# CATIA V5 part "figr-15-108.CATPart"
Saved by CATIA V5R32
Part number: Part1
Bounding box of the stored display mesh (mm): x -60.955 to 60.955, y -33.748 to 33.748, z 0 to 6.052
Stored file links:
  D:\PROJECTS\Project 2022\CATIA V5 6R 2022\Resources\Part Files\c15_catia_v5_6r2022_prt\figr-15-108.CATPart
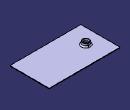
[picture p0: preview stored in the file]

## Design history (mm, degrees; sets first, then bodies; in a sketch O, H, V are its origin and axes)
SheetMetalParameters1: Thickness 1, BendRadius 5, KFactor 0.5 {= log(min(100,max(20*SheetMetalParameters1.BendRadius,SheetMetalParameters1.Thickness)/SheetMetalParameters1.Thickness))/log(100)/2}, ReliefRadialLength 1, ReliefAxialLength 2, MinimumBendRadius 0
Body1 (main body)
  Sketch1 on xy-plane, origin (0, 0, 0), H (1, 0, 0), V (0, 1, 0)
    line L1 (60.9549, 33.7477) -> (60.9549, -33.7477)
    line L2 (60.9549, -33.7477) -> (-60.9549, -33.7477)
    line L3 (-60.9549, -33.7477) -> (-60.9549, 33.7477)
    line L4 (-60.9549, 33.7477) -> (60.9549, 33.7477)
    vertical: L1 V, L3 V
    horizontal: L2 H, L4 H
    equidistance: L1 L3 O, L2 L4 O
  Wall1: Thickness 1, Profile Sketch1
  Sketch2 on face of Wall1, origin (0, 0, 1), H (1, 0, 0), V (0, 1, 0)
    point P1 (-35.8601, 0)
    coincidence: P1 H
  Sketch3 on face of Wall1, origin (-35.8601, 0, 1), H (1, 0, 0), V (0, 1, 0)
    point P1 (0, 0)
    reference projected point E1 (0, 0) from Sketch2.P1
    coincidence: E1 P1
  d_Stamp1: KFacteur 0.5 {= SheetMetalParameters1.KFactor}, Stamp_FilletRadius 2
